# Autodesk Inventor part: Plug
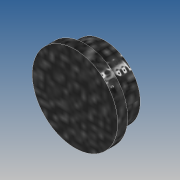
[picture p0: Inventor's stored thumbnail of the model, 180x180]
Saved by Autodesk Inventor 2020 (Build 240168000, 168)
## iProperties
Created: 2019-10
Part Number: Plug
Material: Generic
Document SubType Name: Modeling
Designer: yello
Density: 1 g/cm^3
Appearance: Default
Author: yello
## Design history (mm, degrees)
sketch "Sketch1"
  geometry: C1 r 4.25 at (0, 0); 1 further point
  constraints: 1 centre point, 1 coincident
  dimensions: "d0" = 8.5 diameter of C1
extrude "Extrusion1" new body sketch "Sketch1" distance "d1" = 1; taper "d2" = 0 deg
sketch "Sketch2"
  geometry: C1 r 3.5 at (0, 0); 1 further point
  constraints: 1 centre point, 1 coincident
  dimensions: "d3" = 7 diameter of C1
extrude "Extrusion2" join sketch "Sketch2" distance "d4" = 2; taper "d5" = 0 deg
body "Solid1"
